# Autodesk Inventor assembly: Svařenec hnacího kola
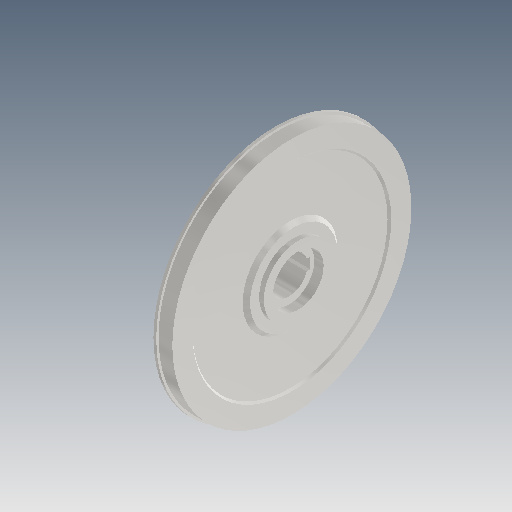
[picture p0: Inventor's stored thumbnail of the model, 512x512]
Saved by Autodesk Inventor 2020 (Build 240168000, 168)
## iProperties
Created: 2025-03
Part Number: Svařenec hnacího kola
Document SubType Name: Assembly
Designer: doma
Mass: 7555.79 g
Surface Area: 1674.79 cm^2
Volume: 962.521 cm^3
Density: 7.85 g/cm^3
Author: doma
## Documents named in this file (3)
- C:\Users\doma\Desktop\Pásovka záloha\Workgroups\NotInProject\Svařenec hnacího kola.iam
- C:\Users\doma\Desktop\Pásovka záloha\Workgroups\NotInProject\Kolo hnací.ipt
- C:\Users\doma\Desktop\Pásovka záloha\Workgroups\NotInProject\Náboj hnacího kola.ipt
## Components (2 placed, 2 different names)
1. Kolo hnací:1 — Proti sobě:1, Proti sobě:2, Stejný směr:1
2. Náboj hnacího kola:1 — Proti sobě:1, Proti sobě:2, Stejný směr:1
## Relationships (3: Mate 2, Flush 1)
- Proti sobě:1 [Mate]: Kolo hnací:1 ↔ Náboj hnacího kola:1
- Proti sobě:2 [Mate]: Kolo hnací:1 ↔ Náboj hnacího kola:1
- Stejný směr:1 [Flush]: Kolo hnací:1 ↔ Náboj hnacího kola:1
